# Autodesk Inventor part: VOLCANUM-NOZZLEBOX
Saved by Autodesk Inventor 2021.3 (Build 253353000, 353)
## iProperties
Created: 2022-12
Part Number: VOLCANUM-NOZZLEBOX
Material: Generic
Document SubType Name: Modeling
Designer: AdminForWorker
Density: 1 g/cm^3
Appearance: Default
Title: VOLCANUM-NOZZLEBOX v8
Author: AdminForWorker
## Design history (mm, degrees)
feature "Body"
body "Solid1"
